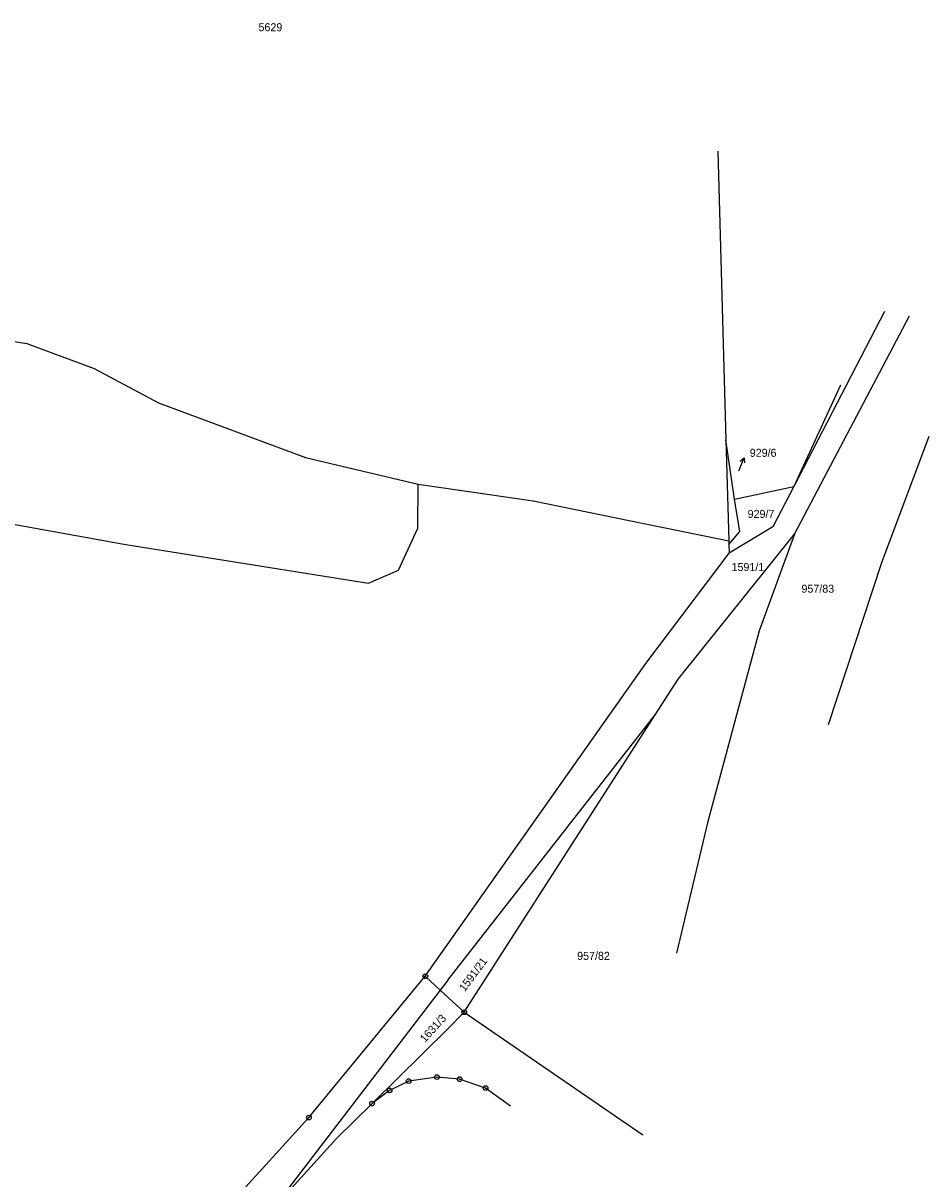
# Model space of a CAD drawing. Extents: x -735092 to -733385, y -1122435 to -1118992.
# Drawn here: x -733577.7 to -733385.2, y -1121933.9 to -1121688.4 of the extents above; entities that cross this region are included whole.
import ezdxf

# ---------------------------------------------------------------- set-up
doc = ezdxf.new("R2010")
doc.units = 0
for name, color, linetype in [('Vrstva 1', 7, 'Continuous'), ('Vrstva 13', 7, 'Continuous'), ('Vrstva 16', 7, 'Continuous'), ('Vrstva 18', 7, 'Continuous'), ('Vrstva 25', 7, 'Continuous')]:
    doc.layers.add(name, color=color, linetype=linetype)

msp = doc.modelspace()

# ---------------------------------------------------------------- linework, layer by layer
at = {"layer": 'Vrstva 1'}
for points in [[(-733394.64, -1121749.67), (-733413.89, -1121786.81)], [(-733413.73, -1121796.96), (-733389.35, -1121750.55)], [(-733601.26, -1121752.62), (-733576.87, -1121756.46)], [(-733576.87, -1121756.46), (-733562.61, -1121761.75)], [(-733562.61, -1121761.75), (-733548.88, -1121769.01)], [(-733404, -1121765.29), (-733413.89, -1121786.81)], [(-733548.88, -1121769.01), (-733517.67, -1121780.69)], [(-733426.49, -1121789.49), (-733428.34, -1121776.9)], [(-733385.2, -1121776.21), (-733395.3, -1121803.03)], [(-733517.67, -1121780.69), (-733493.73, -1121786.33)], [(-733493.83, -1121795.68), (-733493.73, -1121786.33)], [(-733493.73, -1121786.33), (-733469.3, -1121789.9)], [(-733426.49, -1121789.49), (-733413.89, -1121786.81)], [(-733413.89, -1121786.81), (-733418.33, -1121795.39)], [(-733469.3, -1121789.9), (-733446.1, -1121794.59)], [(-733425.41, -1121796.4), (-733426.49, -1121789.49)], [(-733599.06, -1121791.32), (-733555.85, -1121799.14)], [(-733446.1, -1121794.59), (-733429.74, -1121797.93)], [(-733497.92, -1121804.57), (-733493.83, -1121795.68)], [(-733438.48, -1121827.75), (-733413.73, -1121796.96)], [(-733427.71, -1121799.13), (-733425.41, -1121796.4)], [(-733418.33, -1121795.39), (-733427.66, -1121800.95)], [(-733413.73, -1121796.96), (-733421.3, -1121817.5)], [(-733555.85, -1121799.14), (-733504.29, -1121807.35)], [(-733429.74, -1121797.93), (-733427.73, -1121798.34)], [(-733504.29, -1121807.35), (-733497.92, -1121804.57)], [(-733395.3, -1121803.03), (-733406.62, -1121837.45)], [(-733421.3, -1121817.5), (-733432.25, -1121858.28)], [(-733443.37, -1121835.35), (-733438.48, -1121827.75)], [(-733487.43, -1121891.67), (-733443.37, -1121835.35)], [(-733483.95, -1121898.51), (-733443.37, -1121835.35)], [(-733432.25, -1121858.28), (-733438.85, -1121885.99)], [(-733489.05, -1121893.79), (-733492.21, -1121890.86)], [(-733487.43, -1121891.67), (-733489.05, -1121893.79)], [(-733489.05, -1121893.79), (-733524.76, -1121940.41)], [(-733483.95, -1121898.51), (-733489.05, -1121893.79)], [(-733483.95, -1121898.51), (-733487.44, -1121902.01)], [(-733483.95, -1121898.51), (-733445.99, -1121924.53)], [(-733503.53, -1121917.92), (-733487.44, -1121902.01)], [(-733489.76, -1121912.3), (-733495.75, -1121913.13)], [(-733484.93, -1121912.73), (-733489.76, -1121912.3)], [(-733479.4, -1121914.62), (-733484.93, -1121912.73)], [(-733499.81, -1121915.12), (-733503.53, -1121917.92)], [(-733495.75, -1121913.13), (-733499.81, -1121915.12)], [(-733474.12, -1121918.47), (-733479.4, -1121914.62)], [(-733511.06, -1121925.37), (-733503.53, -1121917.92)], [(-733524.76, -1121940.41), (-733511.06, -1121925.37)]]:
    msp.add_lwpolyline(points, dxfattribs=at)
at = {"layer": 'Vrstva 13'}
for points in [[(-733430.08, -1121715.56), (-733428.34, -1121776.9)], [(-733428.34, -1121776.9), (-733427.73, -1121798.34)], [(-733427.73, -1121798.34), (-733427.71, -1121799.13)], [(-733427.71, -1121799.13), (-733427.66, -1121800.95)], [(-733445.37, -1121824.41), (-733427.66, -1121800.95)], [(-733492.21, -1121890.86), (-733445.37, -1121824.41)], [(-733516.96, -1121920.9), (-733492.21, -1121890.86)], [(-733537.34, -1121943.35), (-733516.96, -1121920.9)]]:
    msp.add_lwpolyline(points, dxfattribs=at)
at = {"layer": 'Vrstva 25'}
for points in [[(-733425.57, -1121783.5), (-733424.471, -1121780.709)], [(-733425.303, -1121781.456), (-733424.471, -1121780.709), (-733424.372, -1121781.823)]]:
    msp.add_lwpolyline(points, dxfattribs=at)
for centre, radius in [((-733492.21, -1121890.86), 0.5), ((-733492.21, -1121890.86), 0.5), ((-733492.21, -1121890.86), 0.032), ((-733492.21, -1121890.86), 0.032), ((-733483.95, -1121898.51), 0.5), ((-733483.95, -1121898.51), 0.032), ((-733495.75, -1121913.13), 0.5), ((-733489.76, -1121912.3), 0.5), ((-733489.76, -1121912.3), 0.032), ((-733484.93, -1121912.73), 0.5), ((-733484.93, -1121912.73), 0.032), ((-733499.81, -1121915.12), 0.5), ((-733499.81, -1121915.12), 0.032), ((-733495.75, -1121913.13), 0.032), ((-733479.4, -1121914.62), 0.5), ((-733479.4, -1121914.62), 0.032), ((-733503.53, -1121917.92), 0.5), ((-733503.53, -1121917.92), 0.032), ((-733516.96, -1121920.9), 0.5), ((-733516.96, -1121920.9), 0.5), ((-733516.96, -1121920.9), 0.032), ((-733516.96, -1121920.9), 0.032)]:
    msp.add_circle(centre, radius, dxfattribs=at)

# ---------------------------------------------------------------- texts
at = {"layer": 'Vrstva 16'}
msp.add_text('929/6', height=1.7, dxfattribs=at).set_placement((-733423.27, -1121780.51))
at = {"layer": 'Vrstva 18'}
for s, height, p in [('5629', 1.7, (-733527.66, -1121690.1)), ('929/6', 0.1, (-733427.38, -1121788.41)), ('929/7', 1.7, (-733423.72, -1121793.49)), ('1591/1', 1.7, (-733427.14, -1121804.78)), ('957/83', 1.7, (-733412.28, -1121809.38)), ('957/82', 1.7, (-733459.95, -1121887.38))]:
    msp.add_text(s, height=height, dxfattribs=at).set_placement(p)
for s, rotation, p in [('1591/21', 53.20042, (-733483.85, -1121894.251)), ('1631/3', 47.80038, (-733492.283, -1121905.068))]:
    msp.add_text(s, height=1.7, rotation=rotation, dxfattribs=at).set_placement(p)

doc.saveas('drawing.dxf')
